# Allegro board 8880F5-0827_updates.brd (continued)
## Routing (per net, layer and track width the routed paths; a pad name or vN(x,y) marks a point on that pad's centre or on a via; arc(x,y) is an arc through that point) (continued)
S4_DPS_F_002: length 10.1
  TOP w0.231: 320.65,169.55 321.72,169.55 323.03,170.86 SITE4.3
  TOP w0.508: 320.65,169.55 317.98,166.88 v1(317.98,165.75)
  vias: v1(316.32,162.9) v1(317.98,163.71) v1(511.6,278.76) v1(511.6,276.86)
S4_DPS_F_003: length 63.1
  TOP w0.231: SITE4.107 332.23,200.11 331.69,200.65 331.69,201.16 ; 339.73,169.66 338.57,169.66 336.63,171.59 SITE4.37 ; 329.28,168.85 328.63,169.5 SITE4.17 ; SITE4.145 313.08,188.43 312.83,188.18 ; 314.63,181.63 SITE4.162 ; 347.84,185.53 346.94,186.43 SITE4.71 ; 345.2,182.93 344.9,183.23 SITE4.63
  TOP w0.381: v1(331.94,204.54) 331.69,204.28 331.69,201.16
  TOP w0.508: 312.83,188.18 312.58,187.93 v1(311.44,187.93) ; v1(351.22,181.37) 348.11,181.37 346.8,182.68 345.45,182.68 345.2,182.93 ; v1(351.22,183.91) 349.45,183.91 347.84,185.53 ; 314.63,181.63 314.37,181.63 312.59,183.41 v1(311.44,183.41) ; v1(342.36,165.75) 342.36,167.02 339.73,169.66 ; v1(329.28,165.75) 329.28,168.85
  vias: v1(309.4,187.93) v1(309.4,183.41) v1(329.28,163.71) v1(331.54,192.61) v1(331.94,206.58) v1(342.36,163.71) v1(353.27,183.91) v1(353.27,181.37) v1(464.57,192.28) v1(501.86,278.76) v1(501.86,276.86)
S4_DPS_F_006: length 9.6
  TOP w0.231: SITE4.72 347.92,186.83 348.55,186.19
  TOP w0.508: 348.55,186.19 349.56,185.18 v1(351.22,185.18)
  vias: v1(339,186.67) v1(353.27,185.18) v1(478.58,262.25) v1(478.58,260.35)
S4_DPS_F_007: length 19
  TOP w0.231: SITE4.78 344.15,189.23 344.37,189.01 ; SITE4.97 336.23,200.71 339.65,204.13 v1(339.65,204.54)
  TOP w0.508: v1(351.22,189.5) 350.8,189.5 350.31,189.01 344.37,189.01
  vias: v1(339.65,206.58) v1(353.27,189.5) v1(528.11,262.25) v1(528.11,260.35)
S4_DPS_F_009: length 8.8
  TOP w0.231: 332.26,201.12 332.26,200.9 332.63,200.53 SITE4.106
  TOP w0.381: 332.26,201.12 332.26,203.82 332.83,204.39 v1(332.83,204.54)
  vias: v1(332.83,206.58) v1(333.61,207.66) v1(495.09,262.25) v1(495.09,260.35)
S4_DPS_F_010: length 8.6
  TOP w0.231: SITE4.111 330.63,200.15 331.05,200.57 331.05,201.13
  TOP w0.381: 331.05,201.13 v1(331.05,204.54)
  vias: v1(330.34,193.59) v1(331.05,206.58) v1(485.35,262.25) v1(485.35,260.35)
S4_DPS_F_011: length 17.6
  TOP w0.231: SITE4.119 327.43,197.79 327.64,198.01 ; SITE4.139 314.87,190.83 312.01,193.69 v1(311.44,193.69)
  TOP w0.508: v1(327.57,204.54) 327.64,204.47 327.64,198.01
  vias: v1(309.4,193.69) v1(327.57,206.58) v1(518.37,262.25) v1(518.37,260.35)
S4_DPS_F_012: length 8
  TOP w0.231: 312.2,188.83 SITE4.144
  TOP w0.508: 312.2,188.83 311.81,188.83 v1(311.44,189.2)
  vias: v1(309.4,189.2) v1(468.84,262.25) v1(468.84,260.35)
S4_DPS_F_013:
  vias: v1(117.33,249.71) v1(117.33,247.8) v1(452.62,188.98) v1(457.25,190.45) v1(474.87,173.79) v1(474.89,161.55) v1(474.99,175.15) v1(478.43,173.74) v1(478.43,161.55) v1(478.53,175.15) v1(480.97,161.55) v1(481.07,175.15) v1(482.1,197.87) v1(483.51,161.55) v1(483.61,175.15) v1(489.86,169.47) v1(490.1,183.24)
S4_ISP00+: length 163.7
  TOP w0.086: v1(353.81,185.88) 353.35,186.33 350.29,186.33 349.31,187.31 344.06,187.31 343.98,187.23 SITE4.73
  L30_SIGNAL w0.071: v1(307.81,134.11) 307.81,135.47 307.88,135.54 312.56,135.54 313.46,136.44 313.46,137.88 312.55,138.79 297.11,138.79 293.94,141.95 293.94,193.09 297.8,196.95 305.85,196.95 307.89,198.98 325.62,198.98 327.67,196.93 339.21,196.93 349.79,186.35 353.73,186.35 353.81,186.28 v1(353.81,185.88)
  BOTTOM w0.119: v1(307.81,134.11) UNK4K43.7
S4_ISP00-: length 163.7
  TOP w0.086: v1(353.81,187.02) 353.35,186.57 350.39,186.57 349.41,187.55 344.06,187.55 343.98,187.63 SITE4.74
  L30_SIGNAL w0.071: v1(307.81,137.16) 307.81,135.81 307.88,135.74 312.48,135.74 313.26,136.52 313.26,137.8 312.47,138.59 297.03,138.59 293.74,141.87 293.74,193.17 297.72,197.14 305.76,197.14 307.8,199.18 325.7,199.18 327.75,197.13 339.29,197.13 349.87,186.55 353.73,186.55 353.81,186.62 v1(353.81,187.02)
  BOTTOM w0.119: v1(307.81,137.16) UNK4K43.2
S4_ISP14+: length 147
  TOP w0.086: SITE4.112 330.23,197.78 330.15,197.86 330.15,206.59 331.48,207.92 331.48,209.45 v1(331.93,209.9)
  L28_SIGNAL w0.071: v1(312.21,131.64) 312.21,135.43 312.07,135.56 298.39,135.56 293.47,140.48 293.47,196.62 303.51,206.65 303.51,212.34 304.92,213.75 329.77,213.75 331.46,212.06 331.46,209.97 331.53,209.9 v1(331.93,209.9)
S4_ISP14-: length 146
  TOP w0.086: v1(330.79,209.9) 331.24,209.45 331.24,208.02 329.91,206.69 329.91,197.86 329.83,197.78 SITE4.113
  L28_SIGNAL w0.071: v1(330.79,209.9) 331.19,209.9 331.26,209.97 331.26,211.98 329.69,213.55 305,213.55 303.71,212.26 303.71,206.57 293.67,196.53 293.67,140.56 298.47,135.76 312.08,135.76 312.21,135.89 v1(312.21,139.64)
S4_ISP_1LOCK:
  vias: v1(309.91,185.39)
S4_M_DPS_F_001: length 45.2
  TOP w0.231: 330.63,170.54 SITE4.22 ; 313.24,187.18 313.7,187.63 SITE4.147 ; SITE4.39 337.43,171.49 338.54,170.37 340.57,170.37 ; SITE4.104 333.43,203.21 ; 346.49,183.63 SITE4.64
  TOP w0.381: v1(334.61,204.54) 334.61,204.39 333.43,203.21
  TOP w0.508: v1(330.17,165.75) 330.17,168.96 330.38,169.17 330.38,170.28 330.63,170.54 ; 313.24,187.18 312.72,186.66 v1(311.44,186.66) ; 346.49,183.63 347.49,183.63 348.48,182.64 v1(351.22,182.64) ; 340.57,170.37 343.63,167.31 v1(343.63,165.75)
  vias: v1(309.4,186.66) v1(330.17,163.71) v1(334.61,206.58) v1(343.63,163.71) v1(353.27,182.64) v1(518.37,295.27) v1(518.37,293.37)
S4_PS9G_DCH001: length 3.7
  TOP w0.231: SITE4.18 329.03,170.23 v1(329.63,169.63)
S4_PS9G_DCH002: length 2.2
  TOP w0.231: v1(329.63,171.03) 329.43,171.23 SITE4.19
S4_PS9G_DCH003: length 2.2
  TOP w0.231: v1(331.23,171.03) 331.43,171.23 SITE4.24
S4_PS9G_DCH004: length 2.2
  TOP w0.231: v1(337.63,175.23) 337.83,175.03 SITE4.40
S4_PS9G_DCH005: length 2.2
  TOP w0.231: v1(344.43,175.83) 344.23,176.03 SITE4.45
S4_PS9G_DCH006: length 3.7
  TOP w0.231: v1(345.83,175.83) 345.23,176.43 SITE4.46
S4_PS9G_DCH007: length 5.3
  TOP w0.231: SITE4.47 346.22,176.83 v1(347.22,175.83)
S4_PS9G_DCH009: length 2.2
  TOP w0.231: SITE4.49 344.23,177.63 v1(344.43,177.43)
S4_PS9G_DCH010: length 3.7
  TOP w0.231: v1(345.83,177.43) 345.23,178.03 SITE4.50
S4_PS9G_DCH011: length 5.3
  TOP w0.231: v1(347.22,177.43) 346.22,178.43 SITE4.51
S4_PS9G_DCH014: length 3.7
  TOP w0.231: SITE4.54 345.23,179.63 v1(345.83,179.03)
S4_PS9G_DCH015: length 5.3
  TOP w0.231: SITE4.55 346.22,180.03 v1(347.22,179.03)
S4_PS9G_DCH022: length 5.3
  TOP w0.231: v1(347.22,185.03) 347.05,185.03 346.05,184.03 SITE4.65
S4_PS9G_DCH023: length 2.5
  TOP w0.231: SITE4.66 344.03,184.43 344.43,184.83 v1(344.43,185.03)
S4_PS9G_DCH027: length 3.9
  TOP w0.231: SITE4.70 344.83,186.03 v1(345.83,185.03)
S4_PS9G_DCH028: length 2.3
  TOP w0.231: SITE4.77 340.6,188.83 v1(340.23,188.46)
S4_PS9G_DCH029: length 2.2
  TOP w0.119: SITE4.118 v1(327.83,193.92)
S4_PS9G_DCH030: length 9.2
  TOP w0.231: SITE4.148 317.62,187.23 317.3,186.91 314.16,186.91 312.63,185.39 v1(310.91,185.39)
S4_PS9G_DCH035: length 5.3
  TOP w0.231: v1(314.43,186.23) 315.44,185.23 SITE4.153
S4_PS9G_DCH036: length 2.2
  TOP w0.231: v1(321.43,185.03) 321.23,184.83 SITE4.154
S4_PS9G_DCH037: length 2.2
  TOP w0.231: v1(317.23,184.63) 317.43,184.43 SITE4.155
S4_PS9G_DCH038: length 3.7
  TOP w0.231: SITE4.156 316.43,184.03 v1(315.83,184.63)
S4_PS9G_DCH039: length 5.3
  TOP w0.231: v1(314.43,184.63) 315.44,183.63 SITE4.157
S4_PS9G_DCH040: length 2.2
  TOP w0.231: SITE4.158 321.23,183.23 v1(321.43,183.43)
S4_RLY_001:
  vias: v1(375.22,163.39) v1(415.1,163.64)
S4_RLY_003:
  vias: v1(388.43,163.64) v1(401.89,163.64)
S4_RLY_005:
  vias: v1(375.22,180.15) v1(388.43,180.15)
S4_RLY_007:
  vias: v1(415.61,188.92)
S4_RLY_008:
  vias: v1(375.73,202.38) v1(401.89,180.15)
S4_RLY_016:
  vias: v1(376.23,209.11) v1(392.24,202.38)
S4_RLY_018:
  vias: v1(312.25,216.97)
S4_RLY_021:
  vias: v1(388.43,146.88) v1(402.14,146.88)
S4_RLY_022:
  vias: v1(384.36,131.89) v1(397.57,131.89)
S4_RLY_023:
  vias: v1(410.78,131.89)
S4_RLY_025:
  vias: v1(304.82,146.05) v1(318.32,131.64)
S4_RLY_026:
  vias: v1(346.27,138.37)
S4_RLY_030:
  vias: v1(415.6,146.88)
S4_RLY_043:
  vias: v1(304.61,131.64)
S4_SCAN_DCH008: length 2.2
  TOP w0.231: v1(340.23,177.03) 340.43,177.23 SITE4.48
S4_SCAN_DCH012: length 2.2
  TOP w0.231: SITE4.52 340.43,178.83 v1(340.23,178.63)
S4_SCAN_DCH013: length 2.2
  TOP w0.231: SITE4.53 344.23,179.23 v1(344.43,179.03)
S4_SCAN_DCH016: length 2.2
  TOP w0.231: v1(340.23,180.23) 340.43,180.43 SITE4.56
S4_SCAN_DCH017: length 2.2
  TOP w0.231: v1(344.43,180.63) 344.23,180.83 SITE4.57
S4_SCAN_DCH018: length 3.7
  TOP w0.231: v1(345.83,180.63) 345.23,181.23 SITE4.58
S4_SCAN_DCH019: length 5.3
  TOP w0.231: SITE4.59 346.22,181.63 v1(347.22,180.63)
S4_SCAN_DCH020: length 2.2
  TOP w0.231: v1(340.23,181.83) 340.43,182.03 SITE4.60
S4_SCAN_DCH021: length 2.2
  TOP w0.231: v1(344.43,182.23) 344.23,182.43 SITE4.61
S4_SCAN_DCH024: length 2.2
  TOP w0.231: v1(340.23,184.63) 340.43,184.83 SITE4.67
S4_SCAN_DCH025: length 3.7
  TOP w0.231: SITE4.68 339.43,185.23 v1(338.83,184.63)
S4_SCAN_DCH026: length 5.3
  TOP w0.231: SITE4.69 338.44,185.63 v1(337.44,184.63)
S4_SCAN_DCH031: length 3.7
  TOP w0.231: v1(322.83,187.43) 322.23,186.83 SITE4.149
S4_SCAN_DCH032: length 5.3
  TOP w0.231: SITE4.150 323.22,186.43 v1(324.22,187.43)
S4_SCAN_DCH033: length 2.2
  TOP w0.231: SITE4.151 317.43,186.03 v1(317.23,186.23)
S4_SCAN_DCH034: length 3.7
  TOP w0.231: v1(315.83,186.23) 316.43,185.63 SITE4.152
S4_SPI_1_SCK:
  vias: v1(480.07,175.15)
S4_SPI_1_SDO:
  vias: v1(455.94,166.12)
S4_SPI_2_CSN:
  vias: v1(475.87,173.79)
S4_SPI_2_SCK:
  vias: v1(479.97,161.55)
S4_SPI_2_SDO:
  vias: v1(451.87,166.12)
S4_SPI_11_SDO:
  vias: v1(456.94,166.12) v1(482.61,175.15)
S4_SPI_22_SDI:
  vias: v1(477.43,173.74)
S4_SPI_22_SDO:
  vias: v1(452.87,166.12) v1(482.51,161.55)
S4_SPI_CSN: length 2.2
  TOP w0.231: v1(339.23,171.03) 339.03,171.23 SITE4.43
S4_SPI_SCK: length 2.2
  TOP w0.231: SITE4.42 338.63,175.03 v1(338.83,175.23)
S4_SPI_SDI: length 3.7
  TOP w0.231: SITE4.44 339.43,176.03 v1(338.83,176.63)
S4_SPI_SDO: length 3.7
  TOP w0.231: v1(337.63,176.63) 338.23,176.03 SITE4.41
S4_XTAL_IN: length 2.5
  TOP w0.119: SITE4.109 331.43,198.31 v1(331.63,198.51)
  vias: v1(306.85,211.67)
S4_XTAL_OUT: length 3.7
  TOP w0.231: SITE4.110 331.03,199.03 v1(331.63,199.63)
  vias: v1(306.85,216.97)
UDBGND:
  vias: v1(13.3,262.13) v1(13.55,259.69) v1(23.86,130.71) v1(24.11,128.27) v1(36.83,129.86) v1(117.69,130.81) v1(118.49,128.27) v1(128.57,149.86) v1(128.57,146.05) v1(128.57,138.43) v1(128.57,134.62) v1(130.51,142.24) v1(224.37,298.45) v1(225.17,295.91) v1(452.68,137.92) v1(452.68,134.11) v1(452.68,130.3) v1(454.61,145.54) v1(454.61,141.73) v1(473.29,130.81) v1(474.09,128.27) v1(484.87,130.71) v1(485.12,128.27) v1(512.11,238.76) v1(512.11,234.95) v1(512.11,231.14) v1(512.11,227.33) v1(548.37,300.89) v1(548.62,298.45) v1(557.36,300.99) v1(558.16,298.45)
UT1_UP5V:
  vias: v1(11.05,259.69) v1(11.6,262.13) v1(21.61,128.27) v1(22.16,130.71) v1(36.83,135.89) v1(36.83,133.85) v1(115.19,128.27) v1(115.99,130.81) v1(175.7,264.1) v1(175.7,250.38) v1(175.7,236.67) v1(175.7,222.95) v1(175.7,209.49) v1(175.7,195.52) v1(175.7,182.06) v1(175.7,168.6) v1(175.7,154.88) v1(175.7,141.67) v1(192.47,264.1) v1(192.47,250.38) v1(192.47,236.67) v1(192.47,222.95) v1(192.47,209.49) v1(192.47,195.52) v1(192.47,182.06) v1(192.47,168.6) v1(192.47,154.88) v1(208.98,264.1) v1(209.23,250.38) v1(209.23,236.67) v1(209.23,222.95) v1(209.23,209.49) v1(209.23,195.52) v1(209.49,182.06) v1(209.49,168.6) v1(209.49,155.13) v1(209.49,155.13) v1(221.87,295.91) v1(222.67,298.45) v1(232.25,271.67) v1(232.25,211.67) v1(244.8,288.61) v1(250.5,296.86) v1(256.73,132.14) v1(263.71,296.86) v1(269.69,135.19) v1(273.24,272.1) v1(277.17,296.86) v1(282.9,147.38) v1(290.64,296.86) v1(293.31,272.1) v1(303.84,296.86) v1(304.61,139.64) v1(304.82,154.05) v1(312.25,271.67) v1(312.25,211.67) v1(317.05,296.86) v1(318.32,139.64) v1(330.51,296.86) v1(343.98,296.86) v1(354.27,138.37) v1(369.38,265.11) v1(369.38,249.11) v1(369.38,232.6) v1(369.63,297.12) v1(369.63,281.11) v1(375.22,188.15) v1(375.22,171.39) v1(376.23,217.11) v1(383.09,297.12) v1(383.09,281.11) v1(383.09,265.11) v1(383.09,249.11) v1(383.09,232.85) v1(383.73,202.38) v1(384.36,139.89) v1(388.43,188.15) v1(388.43,171.64) v1(388.43,154.88) v1(389.7,217.36) v1(396.55,297.12) v1(396.55,281.11) v1(396.55,265.37) v1(396.55,249.11) v1(396.55,233.11) v1(397.57,139.89) v1(400.24,202.38) v1(401.89,188.15) v1(401.89,171.64) v1(402.14,154.88) v1(403.41,217.61) v1(410.27,265.37) v1(410.52,297.12) v1(410.52,281.37) v1(410.52,249.11) v1(410.78,139.89) v1(415.1,171.64) v1(415.6,154.88) v1(423.61,188.92) v1(470.79,128.27) v1(471.59,130.81) v1(482.62,128.27) v1(483.17,130.71) v1(546.12,298.45) v1(546.67,300.89) v1(554.86,298.45) v1(555.66,300.99)
N16868442:
  vias: v1(36.83,132.85) v1(36.83,131.76)
N24574244:
  vias: v1(88.53,207.41)
N24574268:
  vias: v1(88.77,221.18)
N24574272:
  vias: v1(93.83,221.18)
N24574311:
  vias: v1(102.1,215.5)
N24574376:
  vias: v1(102.2,229.1)
N24574578:
  vias: v1(93.83,207.46)
N24787993:
  vias: v1(185.21,289.56)
N24789529:
  vias: v1(118.32,288.29)
N24789779:
  vias: v1(168.7,289.56)
N25330426:
  vias: v1(168.7,273.05)
N25334489:
  vias: v1(185.21,273.05)
N25337760:
  vias: v1(201.21,273.05)
N25339188:
  vias: v1(201.21,289.56)
N25462044:
  vias: v1(175.47,273.05)
N25462912:
  vias: v1(158.96,273.05)
N25463486:
  vias: v1(191.48,289.56)
N25464528:
  vias: v1(158.96,289.56)
N25465136:
  vias: v1(175.47,289.56)
N26125600: length 3
  BOTTOM w0.119: K25.3 211.07,244.98 211.54,245.46 R55.2
N26125602: length 3
  BOTTOM w0.119: K25.4 211.07,242.78 211.54,242.31 R56.1
N26125604: length 3
  BOTTOM w0.119: K25.6 199.4,244.98 198.92,245.46 R57.2
N26125606: length 3
  BOTTOM w0.119: K25.5 199.4,242.78 198.92,242.31 R58.1
N26125622: length 3
  BOTTOM w0.119: K26.3 177.54,231.27 178.01,231.74 R59.2
N26125624: length 3
  BOTTOM w0.119: R60.1 178.01,228.6 177.54,229.07 K26.4
N26125626: length 3
  BOTTOM w0.119: R61.2 165.4,231.74 165.87,231.27 K26.6
N26125628: length 3
  BOTTOM w0.119: R62.1 165.4,228.6 165.87,229.07 K26.5
N26125644: length 3
  BOTTOM w0.119: K27.5 182.63,242.78 182.16,242.31 R66.1
N26125646: length 3
  BOTTOM w0.119: K27.6 182.63,244.98 182.16,245.46 R65.2
N26125685: length 3
  BOTTOM w0.119: K22.6 199.4,231.27 198.92,231.74 R45.2
N26125687: length 3
  BOTTOM w0.119: R46.1 198.92,228.6 199.4,229.07 K22.5
N26125689: length 3
  BOTTOM w0.119: K23.3 177.54,217.55 178.01,218.02 R47.2
N26125691: length 3
  BOTTOM w0.119: K23.4 177.54,215.35 178.01,214.88 R48.1
N26125693: length 3
  BOTTOM w0.119: K23.6 165.87,217.55 165.4,218.02 R49.2
N26125695: length 3
  BOTTOM w0.119: R50.1 165.4,214.88 165.87,215.35 K23.5
N26125711: length 3
  BOTTOM w0.119: R51.2 194.78,231.74 194.3,231.27 K24.3
N26125713: length 3
  BOTTOM w0.119: R52.1 194.78,228.6 194.3,229.07 K24.4
N26125715: length 3
  BOTTOM w0.119: K24.6 182.63,231.27 182.16,231.74 R53.2
N26125717: length 3
  BOTTOM w0.119: R54.1 182.16,228.6 182.63,229.07 K24.5
N26125746: length 3
  BOTTOM w0.119: K22.3 211.07,231.27 211.54,231.74 R102.2
N26125748: length 3
  BOTTOM w0.119: R103.1 211.54,228.6 211.07,229.07 K22.4
N26125750: length 3
  BOTTOM w0.119: K27.3 194.3,244.98 194.78,245.46 R104.2
N26125752: length 3
  BOTTOM w0.119: R105.1 194.78,242.31 194.3,242.78 K27.4
N26138300:
  vias: v1(113.29,230.12)
N26138322:
  vias: v1(110.24,230.12)
N26323523: length 3
  BOTTOM w0.119: R71.2 194.78,259.17 194.3,258.7 K17.3
N26323525: length 3
  BOTTOM w0.119: R72.1 194.78,256.03 194.3,256.5 K17.4
N26323527: length 3
  BOTTOM w0.119: R74.1 182.16,256.03 182.63,256.5 K17.5
N26323529: length 3
  BOTTOM w0.119: K17.6 182.63,258.7 182.16,259.17 R73.2
N26323531: length 3
  BOTTOM w0.119: R75.2 211.29,259.17 210.81,258.7 K21.3
N26323533: length 3
  BOTTOM w0.119: K21.4 210.81,256.5 211.29,256.03 R76.1
N26323535: length 3
  BOTTOM w0.119: K21.5 199.14,256.5 198.67,256.03 R78.1
N26323537: length 3
  BOTTOM w0.119: K21.6 199.14,258.7 198.67,259.17 R77.2
N26323539: length 3
  BOTTOM w0.119: R79.2 178.01,259.17 177.54,258.7 K29.3
N26323541: length 3
  BOTTOM w0.119: K29.4 177.54,256.5 178.01,256.03 R80.1
N26323543: length 3
  BOTTOM w0.119: K29.6 165.87,258.7 165.4,259.17 R43.2
N26323545: length 3
  BOTTOM w0.119: R44.1 165.4,256.03 165.87,256.5 K29.5
N26323547: length 3
  BOTTOM w0.119: K30.3 177.54,244.98 178.01,245.46 R63.2
N26323549: length 3
  BOTTOM w0.119: K30.4 177.54,242.78 178.01,242.31 R64.1
N26323551: length 3
  BOTTOM w0.119: K30.5 165.87,242.78 165.4,242.31 R101.1
N26323553: length 3
  BOTTOM w0.119: R100.2 165.4,245.46 165.87,244.98 K30.6
N26325241: length 3
  BOTTOM w0.119: K16.3 239.4,286.77 239.87,286.3 R67.2
N26325243: length 3
  BOTTOM w0.119: R68.1 236.72,286.3 237.2,286.77 K16.4
N26325245: length 3
  BOTTOM w0.119: R70.1 236.72,298.92 237.2,298.44 K16.5
N26325247: length 3
  BOTTOM w0.119: K16.6 239.4,298.44 239.87,298.92 R69.2
N26326910: length 3
  BOTTOM w0.119: R30.1 298.71,286.55 298.24,287.03 K6.5
N26326941: length 3
  BOTTOM w0.119: R27.2 295.56,299.17 296.04,298.7 K6.3
N26326943: length 3
  BOTTOM w0.119: R28.1 298.71,299.17 298.24,298.7 K6.4
N26326945: length 3
  BOTTOM w0.119: R29.2 295.56,286.55 296.04,287.03 K6.6
N26326947: length 3
  BOTTOM w0.119: R34.1 285.25,286.55 284.77,287.03 K7.5
N26326959: length 3
  BOTTOM w0.119: R31.2 282.1,299.17 282.57,298.7 K7.3
N26326961: length 3
  BOTTOM w0.119: K7.4 284.77,298.7 285.25,299.17 R32.1
N26326963: length 3
  BOTTOM w0.119: R33.2 282.1,286.55 282.57,287.03 K7.6
N26327095: length 3
  BOTTOM w0.119: K11.3 255.9,298.7 255.43,299.17 R39.2
N26327097: length 3
  BOTTOM w0.119: K11.4 258.1,298.7 258.58,299.17 R40.1
N26327099: length 3
  BOTTOM w0.119: K8.5 271.31,287.03 271.78,286.55 R38.1
N26327103: length 3
  BOTTOM w0.119: R37.2 268.64,286.55 269.11,287.03 K8.6
N26327105: length 3
  BOTTOM w0.119: R41.2 255.43,286.55 255.9,287.03 K11.6
N26327107: length 3
  BOTTOM w0.119: K11.5 258.1,287.03 258.58,286.55 R42.1
N26328546: length 3
  BOTTOM w0.119: K5.5 311.44,287.03 311.92,286.55 R26.1
N26328550: length 3
  BOTTOM w0.119: R23.2 308.77,299.17 309.24,298.7 K5.3
N26328552: length 3
  BOTTOM w0.119: K5.4 311.44,298.7 311.92,299.17 R24.1
N26328554: length 3
  BOTTOM w0.119: K5.6 309.24,287.03 308.77,286.55 R25.2
N26330264: length 3
  BOTTOM w0.119: K3.5 324.65,287.03 325.12,286.55 R18.1
N26330266: length 3
  BOTTOM w0.119: K3.6 322.45,287.03 321.98,286.55 R17.2
N26330268: length 3
  BOTTOM w0.119: R16.1 325.12,299.17 324.65,298.7 K3.4
N26330270: length 3
  BOTTOM w0.119: R15.2 321.98,299.17 322.45,298.7 K3.3
N26330276: length 3
  BOTTOM w0.119: R10.1 352.05,286.55 351.58,287.03 K1.5
N26330278: length 3
  BOTTOM w0.119: K1.6 349.38,287.03 348.9,286.55 R9.2
N26330280: length 3
  BOTTOM w0.119: K1.4 351.58,298.7 352.05,299.17 R8.1
N26330282: length 3
  BOTTOM w0.119: R7.2 348.9,299.17 349.38,298.7 K1.3
N26330286: length 3
  BOTTOM w0.119: K2.3 335.91,298.7 335.44,299.17 R11.2
N26330288: length 3
  BOTTOM w0.119: K2.4 338.11,298.7 338.59,299.17 R12.1
N26330290: length 3
  BOTTOM w0.119: R22.1 285.24,282.41 285.71,281.93 K4.5
N26330294: length 3
  BOTTOM w0.119: R19.2 288.38,269.79 287.91,270.26 K4.3
N26330296: length 3
  BOTTOM w0.119: K4.4 285.71,270.26 285.24,269.79 R20.1
N26330298: length 3
  BOTTOM w0.119: R21.2 288.38,282.41 287.91,281.93 K4.6
N26330300: length 3
  BOTTOM w0.119: R14.1 338.59,286.55 338.11,287.03 K2.5
N26330302: length 3
  BOTTOM w0.119: K2.6 335.91,287.03 335.44,286.55 R13.2
N26336814:
  vias: v1(123.12,241.1)
N26336816:
  vias: v1(127.7,241.1)
N26336828:
  vias: v1(222.38,273.82) v1(222.38,272.66) v1(224.65,271.67)
N26336832:
  vias: v1(222.38,275.98) v1(222.38,274.82) v1(224.65,276.97)
N26336834:
  vias: v1(221.21,276.98) v1(222.38,276.98)
N26336836:
  vias: v1(221.21,271.66) v1(222.38,271.66)
N26336892:
  vias: v1(127.75,225.81)
N26336894:
  vias: v1(127.75,233.43)
N26337539:
  vias: v1(96.27,241.05)
N26337547:
  vias: v1(96.27,233.43)
N26486525: length 3
  BOTTOM w0.119: UNK2K25.3 415.92,250.95 415.45,251.42 UNK2R55.2
N26486526: length 3
  BOTTOM w0.119: UNK2K25.4 418.12,250.95 418.6,251.42 UNK2R56.1
N26486527: length 3
  BOTTOM w0.119: UNK2K25.6 415.92,239.27 415.45,238.8 UNK2R57.2
N26486528: length 3
  BOTTOM w0.119: UNK2R58.1 418.6,238.8 418.12,239.27 UNK2K25.5
N26486530: length 3
  BOTTOM w0.119: UNK2R59.2 374.3,234.91 374.78,234.44 UNK2K26.3
N26486531: length 3
  BOTTOM w0.119: UNK2K26.4 376.98,234.44 377.45,234.91 UNK2R60.1
N26486532: length 3
  BOTTOM w0.119: UNK2K26.6 374.78,222.76 374.3,222.29 UNK2R61.2
N26486533: length 3
  BOTTOM w0.119: UNK2R62.1 377.45,222.29 376.98,222.76 UNK2K26.5
N26486535: length 3
  BOTTOM w0.119: UNK2K27.5 390.69,223.02 391.16,222.55 UNK2R66.1
N26486536: length 3
  BOTTOM w0.119: UNK2R65.2 388.02,222.55 388.49,223.02 UNK2K27.6
N26486543: length 3
  BOTTOM w0.119: UNK2R45.2 401.48,222.8 401.95,223.27 UNK2K22.6
N26486544: length 3
  BOTTOM w0.119: UNK2R46.1 404.63,222.8 404.15,223.27 UNK2K22.5
N26486545: length 3
  BOTTOM w0.119: UNK2K23.3 408.81,219.45 408.34,219.92 UNK2R47.2
N26486546: length 3
  BOTTOM w0.119: UNK2R48.1 411.48,219.92 411.01,219.45 UNK2K23.4
N26486547: length 3
  BOTTOM w0.119: UNK2R49.2 408.34,207.31 408.81,207.78 UNK2K23.6
N26486548: length 3
  BOTTOM w0.119: UNK2R50.1 411.48,207.31 411.01,207.78 UNK2K23.5
N26486550: length 3
  BOTTOM w0.119: UNK2R51.2 394.62,219.67 395.1,219.2 UNK2K24.3
N26486551: length 3
  BOTTOM w0.119: UNK2K24.4 397.3,219.2 397.77,219.67 UNK2R52.1
N26486552: length 3
  BOTTOM w0.119: UNK2K24.6 395.1,207.52 394.62,207.05 UNK2R53.2
N26486553: length 3
  BOTTOM w0.119: UNK2K24.5 397.3,207.52 397.77,207.05 UNK2R54.1
N26486568: length 3
  BOTTOM w0.119: UNK2K22.3 401.95,234.94 401.48,235.42 UNK2R102.2
N26486569: length 3
  BOTTOM w0.119: UNK2K22.4 404.15,234.94 404.63,235.42 UNK2R103.1
N26486570: length 3
  BOTTOM w0.119: UNK2R104.2 388.02,235.16 388.49,234.69 UNK2K27.3
N26486571: length 3
  BOTTOM w0.119: UNK2K27.4 390.69,234.69 391.16,235.16 UNK2R105.1
N26486686:
  vias: v1(465.57,235.71)
N26486691:
  vias: v1(468.62,235.71)
N26486726: length 3
  BOTTOM w0.119: UNK2R71.2 401.48,299.42 401.95,298.95 UNK2K17.3
N26486727: length 3
  BOTTOM w0.119: UNK2K17.4 404.15,298.95 404.63,299.42 UNK2R72.1
N26486728: length 3
  BOTTOM w0.119: UNK2R74.1 404.63,286.81 404.15,287.28 UNK2K17.5
N26486729: length 3
  BOTTOM w0.119: UNK2K17.6 401.95,287.28 401.48,286.81 UNK2R73.2
N26486730: length 3
  BOTTOM w0.119: UNK2K21.3 375.03,298.95 374.56,299.42 UNK2R75.2
N26486731: length 3
  BOTTOM w0.119: UNK2R76.1 377.7,299.42 377.23,298.95 UNK2K21.4
N26486732: length 3
  BOTTOM w0.119: UNK2K21.5 377.23,287.28 377.7,286.81 UNK2R78.1
N26486733: length 3
  BOTTOM w0.119: UNK2R77.2 374.56,286.81 375.03,287.28 UNK2K21.6
N26486734: length 3
  BOTTOM w0.119: UNK2K29.3 388.49,250.95 388.02,251.42 UNK2R79.2
N26486735: length 3
  BOTTOM w0.119: UNK2R80.1 391.16,251.42 390.69,250.95 UNK2K29.4
N26486736: length 3
  BOTTOM w0.119: UNK2R43.2 388.02,238.8 388.49,239.27 UNK2K29.6
N26486737: length 3
  BOTTOM w0.119: UNK2R44.1 391.16,238.8 390.69,239.27 UNK2K29.5
N26486738: length 3
  BOTTOM w0.119: UNK2R63.2 401.48,251.42 401.95,250.95 UNK2K30.3
N26486739: length 3
  BOTTOM w0.119: UNK2R64.1 404.63,251.42 404.15,250.95 UNK2K30.4
N26486740: length 3
  BOTTOM w0.119: UNK2K30.5 404.15,239.27 404.63,238.8 UNK2R101.1
N26486741: length 3
  BOTTOM w0.119: UNK2K30.6 401.95,239.27 401.48,238.8 UNK2R100.2
N26486822: length 3
  BOTTOM w0.119: UNK2K16.3 375.03,282.95 374.56,283.42 UNK2R67.2
N26486823: length 3
  BOTTOM w0.119: UNK2K16.4 377.23,282.95 377.7,283.42 UNK2R68.1
N26486824: length 3
  BOTTOM w0.119: UNK2R70.1 377.7,270.81 377.23,271.28 UNK2K16.5
N26486825: length 3
  BOTTOM w0.119: UNK2K16.6 375.03,271.28 374.56,270.81 UNK2R69.2
N26486847: length 3
  BOTTOM w0.119: UNK2R30.1 418.6,271.06 418.12,271.53 UNK2K6.5
N26486849: length 3
  BOTTOM w0.119: UNK2K6.3 415.92,283.2 415.45,283.68 UNK2R27.2
N26486850: length 3
  BOTTOM w0.119: UNK2K6.4 418.12,283.2 418.6,283.68 UNK2R28.1
N26486851: length 3
  BOTTOM w0.119: UNK2R29.2 415.45,271.06 415.92,271.53 UNK2K6.6
N26486852: length 3
  BOTTOM w0.119: UNK2K7.5 404.15,271.28 404.63,270.81 UNK2R34.1
N26486854: length 3
  BOTTOM w0.119: UNK2R31.2 401.48,283.42 401.95,282.95 UNK2K7.3
N26486855: length 3
  BOTTOM w0.119: UNK2R32.1 404.63,283.42 404.15,282.95 UNK2K7.4
N26486856: length 3
  BOTTOM w0.119: UNK2R33.2 401.48,270.81 401.95,271.28 UNK2K7.6
N26486898: length 3
  BOTTOM w0.119: UNK2R39.2 388.02,283.42 388.49,282.95 UNK2K11.3
N26486899: length 3
  BOTTOM w0.119: UNK2K11.4 390.69,282.95 391.16,283.42 UNK2R40.1
N26486900: length 3
  BOTTOM w0.119: UNK2K8.5 390.69,287.28 391.16,286.81 UNK2R38.1
N26486902: length 3
  BOTTOM w0.119: UNK2K8.6 388.49,287.28 388.02,286.81 UNK2R37.2
N26486903: length 3
  BOTTOM w0.119: UNK2K11.6 388.49,271.28 388.02,270.81 UNK2R41.2
N26486904: length 3
  BOTTOM w0.119: UNK2R42.1 391.16,270.81 390.69,271.28 UNK2K11.5
N26486946: length 3
  BOTTOM w0.119: UNK2K5.5 417.87,255.53 418.34,255.06 UNK2R26.1
N26486948: length 3
  BOTTOM w0.119: UNK2R23.2 415.2,267.67 415.67,267.2 UNK2K5.3
N26486949: length 3
  BOTTOM w0.119: UNK2K5.4 417.87,267.2 418.34,267.67 UNK2R24.1
N26486950: length 3
  BOTTOM w0.119: UNK2K5.6 415.67,255.53 415.2,255.06 UNK2R25.2
N26486971: length 3
  BOTTOM w0.119: UNK2K3.5 404.15,255.53 404.63,255.06 UNK2R18.1
N26486972: length 3
  BOTTOM w0.119: UNK2K3.6 401.95,255.53 401.48,255.06 UNK2R17.2
N26486973: length 3
  BOTTOM w0.119: UNK2K3.4 404.15,267.2 404.63,267.67 UNK2R16.1
N26486974: length 3
  BOTTOM w0.119: UNK2R15.2 401.48,267.67 401.95,267.2 UNK2K3.3
N26486977: length 3
  BOTTOM w0.119: UNK2R10.1 418.6,286.81 418.12,287.28 UNK2K1.5
N26486978: length 3
  BOTTOM w0.119: UNK2R9.2 415.45,286.81 415.92,287.28 UNK2K1.6
N26486979: length 3
  BOTTOM w0.119: UNK2R8.1 418.6,299.42 418.12,298.95 UNK2K1.4
N26486980: length 3
  BOTTOM w0.119: UNK2K1.3 415.92,298.95 415.45,299.42 UNK2R7.2
N26486982: length 3
  BOTTOM w0.119: UNK2K2.3 374.78,250.95 374.3,251.42 UNK2R11.2
N26486983: length 3
  BOTTOM w0.119: UNK2R12.1 377.45,251.42 376.98,250.95 UNK2K2.4
N26486984: length 3
  BOTTOM w0.119: UNK2K4.5 376.98,255.28 377.45,254.8 UNK2R22.1
N26486986: length 3
  BOTTOM w0.119: UNK2K4.3 374.78,266.95 374.3,267.42 UNK2R19.2
N26486987: length 3
  BOTTOM w0.119: UNK2R20.1 377.45,267.42 376.98,266.95 UNK2K4.4
N26486988: length 3
  BOTTOM w0.119: UNK2K4.6 374.78,255.28 374.3,254.8 UNK2R21.2
N26486989: length 3
  BOTTOM w0.119: UNK2K2.5 376.98,239.27 377.45,238.8 UNK2R14.1
N26486990: length 3
  BOTTOM w0.119: UNK2R13.2 374.3,238.8 374.78,239.27 UNK2K2.6
N26487182:
  vias: v1(456.25,233.88)
N26487183:
  vias: v1(451.68,233.88)
N26487190:
  vias: v1(302.38,273.82) v1(302.38,272.66) v1(304.65,271.67)
N26487192:
  vias: v1(302.38,275.98) v1(302.38,274.82) v1(304.65,276.97)
N26487193:
  vias: v1(301.21,276.98) v1(302.38,276.98)
N26487194:
  vias: v1(301.21,271.66) v1(302.38,271.66)
N26487223:
  vias: v1(451.62,232.41)
N26487224:
  vias: v1(451.62,224.79)
N26487285:
  vias: v1(483.1,233.68)
N26487289:
  vias: v1(483.1,241.3)
N26491412:
  vias: v1(491.1,226.67)
N26491416:
  vias: v1(490.86,212.91)
N26491418:
  vias: v1(485.8,212.91)
N26491425:
  vias: v1(477.53,218.59)
N26491459:
  vias: v1(477.43,204.98)
N26491497:
  vias: v1(485.8,226.62)
N26492255:
  vias: v1(462.07,290.83)
N26492261:
  vias: v1(485.35,290.83)
N26492266:
  vias: v1(462.07,274.32)
N26492386:
  vias: v1(478.58,274.32)
N26492392:
  vias: v1(495.09,274.32)
N26492464:
  vias: v1(511.6,290.83)
N26492470:
  vias: v1(478.58,290.83)
N26492603:
  vias: v1(485.35,274.32)
N26492609:
  vias: v1(468.84,274.32)
N26492613:
  vias: v1(468.84,290.83)
N26492615:
  vias: v1(452.33,274.32)
N26492621:
  vias: v1(452.33,290.83)
N26495382: length 3
  BOTTOM w0.119: UNK3K25.3 177.54,149.48 178.01,149.95 UNK3R55.2
N26495383: length 3
  BOTTOM w0.119: UNK3R56.1 178.01,146.81 177.54,147.28 UNK3K25.4
N26495384: length 3
  BOTTOM w0.119: UNK3R57.2 165.4,149.95 165.87,149.48 UNK3K25.6
N26495385: length 3
  BOTTOM w0.119: UNK3K25.5 165.87,147.28 165.4,146.81 UNK3R58.1
N26495387: length 3
  BOTTOM w0.119: UNK3R59.2 194.78,163.67 194.3,163.2 UNK3K26.3
N26495388: length 3
  BOTTOM w0.119: UNK3K26.4 194.3,161 194.78,160.52 UNK3R60.1
N26495389: length 3
  BOTTOM w0.119: UNK3R61.2 182.16,163.67 182.63,163.2 UNK3K26.6
N26495390: length 3
  BOTTOM w0.119: UNK3K26.5 182.63,161 182.16,160.52 UNK3R62.1
N26495392: length 3
  BOTTOM w0.119: UNK3K27.5 199.65,161 199.18,160.52 UNK3R66.1
N26495393: length 3
  BOTTOM w0.119: UNK3R65.2 199.18,163.67 199.65,163.2 UNK3K27.6
N26495400: length 3
  BOTTOM w0.119: UNK3R45.2 165.4,136.74 165.87,136.27 UNK3K22.6
N26495401: length 3
  BOTTOM w0.119: UNK3K22.5 165.87,134.07 165.4,133.6 UNK3R46.1
N26495402: length 3
  BOTTOM w0.119: UNK3K23.3 211.32,149.73 211.79,150.21 UNK3R47.2
N26495403: length 3
  BOTTOM w0.119: UNK3K23.4 211.32,147.53 211.79,147.06 UNK3R48.1
N26495404: length 3
  BOTTOM w0.119: UNK3K23.6 199.65,149.73 199.18,150.21 UNK3R49.2
N26495405: length 3
  BOTTOM w0.119: UNK3R50.1 199.18,147.06 199.65,147.53 UNK3K23.5
N26495407: length 3
  BOTTOM w0.119: UNK3K24.3 194.3,149.48 194.78,149.95 UNK3R51.2
N26495408: length 3
  BOTTOM w0.119: UNK3K24.4 194.3,147.28 194.78,146.81 UNK3R52.1
N26495409: length 3
  BOTTOM w0.119: UNK3R53.2 182.16,149.95 182.63,149.48 UNK3K24.6
N26495410: length 3
  BOTTOM w0.119: UNK3R54.1 182.16,146.81 182.63,147.28 UNK3K24.5
N26495425: length 3
  BOTTOM w0.119: UNK3R102.2 178.01,136.74 177.54,136.27 UNK3K22.3
N26495426: length 3
  BOTTOM w0.119: UNK3R103.1 178.01,133.6 177.54,134.07 UNK3K22.4
N26495427: length 3
  BOTTOM w0.119: UNK3K27.3 211.32,163.2 211.79,163.67 UNK3R104.2
N26495428: length 3
  BOTTOM w0.119: UNK3R105.1 211.79,160.52 211.32,161 UNK3K27.4
N26495543:
  vias: v1(113.55,186.44)
N26495548:
  vias: v1(110.5,186.44)
N26495583: length 3
  BOTTOM w0.119: UNK3K17.3 177.54,190.12 178.01,190.59 UNK3R71.2
N26495584: length 3
  BOTTOM w0.119: UNK3K17.4 177.54,187.92 178.01,187.45 UNK3R72.1
N26495585: length 3
  BOTTOM w0.119: UNK3R74.1 165.4,187.45 165.87,187.92 UNK3K17.5
N26495586: length 3
  BOTTOM w0.119: UNK3R73.2 165.4,190.59 165.87,190.12 UNK3K17.6
N26495587: length 3
  BOTTOM w0.119: UNK3K21.3 211.07,190.12 211.54,190.59 UNK3R75.2
N26495588: length 3
  BOTTOM w0.119: UNK3R76.1 211.54,187.45 211.07,187.92 UNK3K21.4
N26495589: length 3
  BOTTOM w0.119: UNK3K21.5 199.4,187.92 198.92,187.45 UNK3R78.1
N26495590: length 3
  BOTTOM w0.119: UNK3R77.2 198.92,190.59 199.4,190.12 UNK3K21.6
N26495591: length 3
  BOTTOM w0.119: UNK3K29.3 211.32,176.66 211.79,177.13 UNK3R79.2
N26495592: length 3
  BOTTOM w0.119: UNK3K29.4 211.32,174.46 211.79,173.99 UNK3R80.1
N26495593: length 3
  BOTTOM w0.119: UNK3R43.2 199.18,177.13 199.65,176.66 UNK3K29.6
N26495594: length 3
  BOTTOM w0.119: UNK3R44.1 199.18,173.99 199.65,174.46 UNK3K29.5
N26495595: length 3
  BOTTOM w0.119: UNK3R63.2 178.01,163.67 177.54,163.2 UNK3K30.3
N26495596: length 3
  BOTTOM w0.119: UNK3R64.1 178.01,160.52 177.54,161 UNK3K30.4
N26495597: length 3
  BOTTOM w0.119: UNK3R101.1 165.4,160.52 165.87,161 UNK3K30.5
N26495598: length 3
  BOTTOM w0.119: UNK3R100.2 165.4,163.67 165.87,163.2 UNK3K30.6
N26495679: length 3
  BOTTOM w0.119: UNK3K16.3 211.07,204.09 211.54,204.56 UNK3R67.2
N26495680: length 3
  BOTTOM w0.119: UNK3R68.1 211.54,201.42 211.07,201.89 UNK3K16.4
N26495681: length 3
  BOTTOM w0.119: UNK3R70.1 198.92,201.42 199.4,201.89 UNK3K16.5
N26495682: length 3
  BOTTOM w0.119: UNK3R69.2 198.92,204.56 199.4,204.09 UNK3K16.6
N26495704: length 3
  BOTTOM w0.119: UNK3K6.5 182.63,215.35 182.16,214.88 UNK3R30.1
N26495706: length 3
  BOTTOM w0.119: UNK3K6.3 194.3,217.55 194.78,218.02 UNK3R27.2
N26495707: length 3
  BOTTOM w0.119: UNK3K6.4 194.3,215.35 194.78,214.88 UNK3R28.1
N26495708: length 3
  BOTTOM w0.119: UNK3K6.6 182.63,217.55 182.16,218.02 UNK3R29.2
N26495709: length 3
  BOTTOM w0.119: UNK3K7.5 182.63,201.89 182.16,201.42 UNK3R34.1
N26495711: length 3
  BOTTOM w0.119: UNK3K7.3 194.3,204.09 194.78,204.56 UNK3R31.2
N26495712: length 3
  BOTTOM w0.119: UNK3K7.4 194.3,201.89 194.78,201.42 UNK3R32.1
N26495713: length 3
  BOTTOM w0.119: UNK3R33.2 182.16,204.56 182.63,204.09 UNK3K7.6
N26495755: length 3
  BOTTOM w0.119: UNK3K11.3 177.54,204.09 178.01,204.56 UNK3R39.2
N26495756: length 3
  BOTTOM w0.119: UNK3R40.1 178.01,201.42 177.54,201.89 UNK3K11.4
N26495757: length 3
  BOTTOM w0.119: UNK3K8.5 182.63,187.92 182.16,187.45 UNK3R38.1
N26495759: length 3
  BOTTOM w0.119: UNK3K8.6 182.63,190.12 182.16,190.59 UNK3R37.2
N26495760: length 3
  BOTTOM w0.119: UNK3K11.6 165.87,204.09 165.4,204.56 UNK3R41.2
N26495761: length 3
  BOTTOM w0.119: UNK3R42.1 165.4,201.42 165.87,201.89 UNK3K11.5
N26495803: length 3
  BOTTOM w0.119: UNK3R26.1 198.92,214.88 199.4,215.35 UNK3K5.5
N26495805: length 3
  BOTTOM w0.119: UNK3K5.3 211.07,217.55 211.54,218.02 UNK3R23.2
N26495806: length 3
  BOTTOM w0.119: UNK3K5.4 211.07,215.35 211.54,214.88 UNK3R24.1
N26495807: length 3
  BOTTOM w0.119: UNK3K5.6 199.4,217.55 198.92,218.02 UNK3R25.2
N26495828: length 3
  BOTTOM w0.119: UNK3R18.1 261.62,145.5 262.09,145.03 UNK3K3.5
N26495829: length 3
  BOTTOM w0.119: UNK3K3.6 264.29,145.03 264.76,145.5 UNK3R17.2
N26495830: length 3
  BOTTOM w0.119: UNK3R16.1 261.62,132.88 262.09,133.36 UNK3K3.4
N26495831: length 3
  BOTTOM w0.119: UNK3R15.2 264.76,132.88 264.29,133.36 UNK3K3.3
N26495834: length 3
  BOTTOM w0.119: UNK3R10.1 165.4,173.99 165.87,174.46 UNK3K1.5
N26495835: length 3
  BOTTOM w0.119: UNK3K1.6 165.87,176.66 165.4,177.13 UNK3R9.2
N26495836: length 3
  BOTTOM w0.119: UNK3R8.1 178.01,173.99 177.54,174.46 UNK3K1.4
N26495837: length 3
  BOTTOM w0.119: UNK3R7.2 178.01,177.13 177.54,176.66 UNK3K1.3
N26495839: length 3
  BOTTOM w0.119: UNK3K2.3 251.33,130.31 251.81,129.84 UNK3R11.2
N26495840: length 3
  BOTTOM w0.119: UNK3K2.4 249.13,130.31 248.66,129.84 UNK3R12.1
N26495841: length 3
  BOTTOM w0.119: UNK3K4.5 275.3,157.22 274.82,157.69 UNK3R22.1
N26495843: length 3
  BOTTOM w0.119: UNK3K4.3 277.5,145.55 277.97,145.08 UNK3R19.2
N26495844: length 3
  BOTTOM w0.119: UNK3R20.1 274.82,145.08 275.3,145.55 UNK3K4.4
N26495845: length 3
  BOTTOM w0.119: UNK3R21.2 277.97,157.69 277.5,157.22 UNK3K4.6
N26495846: length 3
  BOTTOM w0.119: UNK3K2.5 249.13,141.98 248.66,142.45 UNK3R14.1
N26495847: length 3
  BOTTOM w0.119: UNK3K2.6 251.33,141.98 251.81,142.45 UNK3R13.2
N26496039:
  vias: v1(123.38,197.41)
N26496040:
  vias: v1(127.95,197.41)
N26496047:
  vias: v1(222.38,213.82) v1(222.38,212.66) v1(224.65,211.67)
N26496049:
  vias: v1(222.38,215.98) v1(222.38,214.82) v1(224.65,216.97)
N26496050:
  vias: v1(221.21,216.98) v1(222.38,216.98)
N26496051:
  vias: v1(221.21,211.66) v1(222.38,211.66)
N26496080:
  vias: v1(128.01,182.12)
N26496081:
  vias: v1(128.01,189.74)
N26496142:
  vias: v1(96.53,197.36)
N26496146:
  vias: v1(96.53,189.74)
N26500269:
  vias: v1(88.78,163.72)
N26500273:
  vias: v1(89.02,177.49)
N26500275:
  vias: v1(94.09,177.49)
N26500282:
  vias: v1(102.35,171.81)
N26500316:
  vias: v1(102.45,185.42)
N26500354:
  vias: v1(94.09,163.77)
N26501112:
  vias: v1(111.55,288.29)
N26501118:
  vias: v1(101.81,271.78)
N26501123:
  vias: v1(128.06,271.78)
N26501243:
  vias: v1(75.99,271.78)
N26501249:
  vias: v1(75.99,288.29)
N26501321:
  vias: v1(93.77,271.78)
N26501327:
  vias: v1(93.77,288.29)
N26501460:
  vias: v1(66.25,288.29)
N26501466:
  vias: v1(66.25,271.78)
N26501470:
  vias: v1(84.03,288.29)
N26501472:
  vias: v1(118.32,271.78)
N26501478:
  vias: v1(101.81,288.29)
N26504239: length 3
  BOTTOM w0.119: UNK4R55.2 309.75,156.36 310.22,155.89 UNK4K25.3
N26504240: length 3
  BOTTOM w0.119: UNK4K25.4 312.42,155.89 312.89,156.36 UNK4R56.1
N26504241: length 3
  BOTTOM w0.119: UNK4K25.6 310.22,144.21 309.75,143.74 UNK4R57.2
N26504242: length 3
  BOTTOM w0.119: UNK4K25.5 312.42,144.21 312.89,143.74 UNK4R58.1
N26504244: length 3
  BOTTOM w0.119: UNK4R59.2 356.57,133.44 356.1,132.97 UNK4K26.3
N26504245: length 3
  BOTTOM w0.119: UNK4R60.1 356.57,130.3 356.1,130.77 UNK4K26.4
N26504246: length 3
  BOTTOM w0.119: UNK4K26.6 344.43,132.97 343.96,133.44 UNK4R61.2
N26504247: length 3
  BOTTOM w0.119: UNK4R62.1 343.96,130.3 344.43,130.77 UNK4K26.5
N26504249: length 3
  BOTTOM w0.119: UNK4K27.5 325.92,129.8 326.39,129.33 UNK4R66.1
N26504250: length 3
  BOTTOM w0.119: UNK4R65.2 323.25,129.33 323.72,129.8 UNK4K27.6
N26504257: length 3
  BOTTOM w0.119: UNK4K22.6 389.76,130.05 389.29,129.58 UNK4R45.2
N26504258: length 3
  BOTTOM w0.119: UNK4R46.1 392.43,129.58 391.96,130.05 UNK4K22.5
N26504259: length 3
  BOTTOM w0.119: UNK4R47.2 415.71,142.2 416.18,141.73 UNK4K23.3
N26504260: length 3
  BOTTOM w0.119: UNK4K23.4 418.38,141.73 418.85,142.2 UNK4R48.1
N26504261: length 3
  BOTTOM w0.119: UNK4K23.6 416.18,130.05 415.71,129.58 UNK4R49.2
N26504262: length 3
  BOTTOM w0.119: UNK4K23.5 418.38,130.05 418.85,129.58 UNK4R50.1
N26504264: length 3
  BOTTOM w0.119: UNK4R51.2 402.5,142.2 402.97,141.73 UNK4K24.3
N26504265: length 3
  BOTTOM w0.119: UNK4R52.1 405.64,142.2 405.17,141.73 UNK4K24.4
N26504266: length 3
  BOTTOM w0.119: UNK4R53.2 402.5,129.58 402.97,130.05 UNK4K24.6
N26504267: length 3
  BOTTOM w0.119: UNK4R54.1 405.64,129.58 405.17,130.05 UNK4K24.5
N26504282: length 3
  BOTTOM w0.119: UNK4K22.3 389.76,141.73 389.29,142.2 UNK4R102.2
N26504283: length 3
  BOTTOM w0.119: UNK4K22.4 391.96,141.73 392.43,142.2 UNK4R103.1
N26504284: length 3
  BOTTOM w0.119: UNK4K27.3 323.72,141.47 323.25,141.94 UNK4R104.2
N26504285: length 3
  BOTTOM w0.119: UNK4K27.4 325.92,141.47 326.39,141.94 UNK4R105.1
N26504400:
  vias: v1(465.57,192.28)
N26504405:
  vias: v1(468.62,192.28)
N26504440: length 3
  BOTTOM w0.119: UNK4R71.2 381.16,219.41 381.63,218.94 UNK4K17.3
N26504441: length 3
  BOTTOM w0.119: UNK4K17.4 383.83,218.94 384.31,219.41 UNK4R72.1
N26504442: length 3
  BOTTOM w0.119: UNK4R74.1 384.31,206.8 383.83,207.27 UNK4K17.5
N26504443: length 3
  BOTTOM w0.119: UNK4R73.2 381.16,206.8 381.63,207.27 UNK4K17.6
N26504444: length 3
  BOTTOM w0.119: UNK4R75.2 393.35,157.18 393.83,156.71 UNK4K21.3
N26504445: length 3
  BOTTOM w0.119: UNK4K21.4 396.03,156.71 396.5,157.18 UNK4R76.1
N26504446: length 3
  BOTTOM w0.119: UNK4R78.1 396.5,144.57 396.03,145.04 UNK4K21.5
N26504447: length 3
  BOTTOM w0.119: UNK4K21.6 393.83,145.04 393.35,144.57 UNK4R77.2
N26504448: length 3
  BOTTOM w0.119: UNK4R79.2 407.07,157.18 407.54,156.71 UNK4K29.3
N26504449: length 3
  BOTTOM w0.119: UNK4R80.1 410.21,157.18 409.74,156.71 UNK4K29.4
N26504450: length 3
  BOTTOM w0.119: UNK4R43.2 407.07,144.57 407.54,145.04 UNK4K29.6
N26504451: length 3
  BOTTOM w0.119: UNK4R44.1 410.21,144.57 409.74,145.04 UNK4K29.5
N26504452: length 3
  BOTTOM w0.119: UNK4K30.3 421,156.71 420.53,157.18 UNK4R63.2
N26504453: length 3
  BOTTOM w0.119: UNK4R64.1 423.68,157.18 423.2,156.71 UNK4K30.4
N26504454: length 3
  BOTTOM w0.119: UNK4R101.1 423.68,144.57 423.2,145.04 UNK4K30.5
N26504455: length 3
  BOTTOM w0.119: UNK4K30.6 421,145.04 420.53,144.57 UNK4R100.2
N26504536: length 3
  BOTTOM w0.119: UNK4K16.3 402.08,196.98 402.55,197.45 UNK4R67.2
N26504537: length 3
  BOTTOM w0.119: UNK4K16.4 402.08,194.78 402.55,194.31 UNK4R68.1
N26504538: length 3
  BOTTOM w0.119: UNK4K16.5 390.4,194.78 389.93,194.31 UNK4R70.1
N26504539: length 3
  BOTTOM w0.119: UNK4R69.2 389.93,197.45 390.4,196.98 UNK4K16.6
N26504561: length 3
  BOTTOM w0.119: UNK4R30.1 396.5,177.84 396.03,178.31 UNK4K6.5
N26504563: length 3
  BOTTOM w0.119: UNK4K6.3 393.83,189.99 393.35,190.46 UNK4R27.2
N26504564: length 3
  BOTTOM w0.119: UNK4R28.1 396.5,190.46 396.03,189.99 UNK4K6.4
N26504565: length 3
  BOTTOM w0.119: UNK4R29.2 393.35,177.84 393.83,178.31 UNK4K6.6
N26504566: length 3
  BOTTOM w0.119: UNK4K7.5 413.77,181.32 413.3,180.84 UNK4R34.1
N26504568: length 3
  BOTTOM w0.119: UNK4R31.2 425.92,183.99 425.44,183.52 UNK4K7.3
N26504569: length 3
  BOTTOM w0.119: UNK4K7.4 425.44,181.32 425.92,180.84 UNK4R32.1
N26504570: length 3
  BOTTOM w0.119: UNK4K7.6 413.77,183.52 413.3,183.99 UNK4R33.2
N26504612: length 3
  BOTTOM w0.119: UNK4K11.3 385.57,196.98 386.04,197.45 UNK4R39.2
N26504613: length 3
  BOTTOM w0.119: UNK4K11.4 385.57,194.78 386.04,194.31 UNK4R40.1
N26504614: length 3
  BOTTOM w0.119: UNK4R38.1 409.96,177.84 409.49,178.31 UNK4K8.5
N26504616: length 3
  BOTTOM w0.119: UNK4R37.2 406.82,177.84 407.29,178.31 UNK4K8.6
N26504617: length 3
  BOTTOM w0.119: UNK4K11.6 373.89,196.98 373.42,197.45 UNK4R41.2
N26504618: length 3
  BOTTOM w0.119: UNK4K11.5 373.89,194.78 373.42,194.31 UNK4R42.1
N26504660: length 3
  BOTTOM w0.119: UNK4K5.5 382.82,178.31 383.29,177.84 UNK4R26.1
N26504662: length 3
  BOTTOM w0.119: UNK4R23.2 380.15,190.46 380.62,189.99 UNK4K5.3
N26504663: length 3
  BOTTOM w0.119: UNK4K5.4 382.82,189.99 383.29,190.46 UNK4R24.1
N26504664: length 3
  BOTTOM w0.119: UNK4R25.2 380.15,177.84 380.62,178.31 UNK4K5.6
N26504685: length 3
  BOTTOM w0.119: UNK4K3.5 396.03,161.8 396.5,161.33 UNK4R18.1
N26504686: length 3
  BOTTOM w0.119: UNK4K3.6 393.83,161.8 393.35,161.33 UNK4R17.2
N26504687: length 3
  BOTTOM w0.119: UNK4R16.1 396.5,173.95 396.03,173.48 UNK4K3.4
N26504688: length 3
  BOTTOM w0.119: UNK4K3.3 393.83,173.48 393.35,173.95 UNK4R15.2
N26504691: length 3
  BOTTOM w0.119: UNK4R10.1 423.17,161.33 422.7,161.8 UNK4K1.5
N26504692: length 3
  BOTTOM w0.119: UNK4K1.6 420.5,161.8 420.02,161.33 UNK4R9.2
N26504693: length 3
  BOTTOM w0.119: UNK4K1.4 422.7,173.48 423.17,173.95 UNK4R8.1
N26504694: length 3
  BOTTOM w0.119: UNK4K1.3 420.5,173.48 420.02,173.95 UNK4R7.2
N26504696: length 3
  BOTTOM w0.119: UNK4K2.3 380.62,173.22 380.15,173.69 UNK4R11.2
N26504697: length 3
  BOTTOM w0.119: UNK4K2.4 382.82,173.22 383.29,173.69 UNK4R12.1
N26504698: length 3
  BOTTOM w0.119: UNK4R22.1 409.96,161.33 409.49,161.8 UNK4K4.5
N26504700: length 3
  BOTTOM w0.119: UNK4K4.3 407.29,173.48 406.82,173.95 UNK4R19.2
N26504701: length 3
  BOTTOM w0.119: UNK4R20.1 409.96,173.95 409.49,173.48 UNK4K4.4
N26504702: length 3
  BOTTOM w0.119: UNK4K4.6 407.29,161.8 406.82,161.33 UNK4R21.2
N26504703: length 3
  BOTTOM w0.119: UNK4K2.5 382.82,161.55 383.29,161.08 UNK4R14.1
N26504704: length 3
  BOTTOM w0.119: UNK4R13.2 380.15,161.08 380.62,161.55 UNK4K2.6
N26504896:
  vias: v1(456.25,190.45)
N26504897:
  vias: v1(451.68,190.45)
N26504904:
  vias: v1(302.38,213.82) v1(302.38,212.66) v1(304.65,211.67)
N26504906:
  vias: v1(302.38,215.98) v1(302.38,214.82) v1(304.65,216.97)
N26504907:
  vias: v1(301.21,216.98) v1(302.38,216.98)
N26504908:
  vias: v1(301.21,211.66) v1(302.38,211.66)
N26504937:
  vias: v1(451.62,188.98)
N26505003:
  vias: v1(483.1,197.87)
N26509126:
  vias: v1(491.1,183.24)
N26509130:
  vias: v1(490.86,169.47)
N26509132:
  vias: v1(485.8,169.47)
N26509139:
  vias: v1(477.53,175.15)
N26509173:
  vias: v1(477.43,161.55)
N26509211:
  vias: v1(485.8,183.19)
N26509969:
  vias: v1(511.6,274.32)
N26509975:
  vias: v1(518.37,290.83)
N26509980:
  vias: v1(528.11,274.32)
N26510100:
  vias: v1(478.58,257.81)
N26510106:
  vias: v1(528.11,257.81)
N26510178:
  vias: v1(511.6,257.81)
N26510184:
  vias: v1(495.09,257.81)
N26510317:
  vias: v1(518.37,257.81)
N26510323:
  vias: v1(468.84,257.81)
N26510327:
  vias: v1(485.35,257.81)
N26510329:
  vias: v1(518.37,274.32)
N26510335:
  vias: v1(501.86,274.32)

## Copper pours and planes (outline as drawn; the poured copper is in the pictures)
GND on L02_DGND, L03_SIGNAL, L04_DGND, L05_SIGNAL, L06_DGND, L07_SIGNAL, L08_DGND, L10_DGND, L12_DGND, L14_DGND, L16_DGND, L19_DGND, L21_DGND, L23_DGND, L25_DGND, L27_DGND, L28_SIGNAL, L29_DGND, L30_SIGNAL, L31_DGND: 1.02,1.27 1.02,427.99 205.54,427.99 216.92,422.32 228.3,427.99 352.84,427.99 364.23,422.27 375.62,427.99 580.13,427.99 580.13,1.27 301.95,1.27 290.57,6.93 279.19,1.27
(no net) on L32_SIGNAL, L33_DGND: 1.02,1.27 1.02,427.99 205.54,427.99 216.92,422.32 228.3,427.99 352.84,427.99 364.23,422.27 375.62,427.99 580.13,427.99 580.13,1.27 301.95,1.27 290.57,6.93 279.19,1.27

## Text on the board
User.Comments: CR_SS_6 | CR_2_2 | CR_RELAY_19 | CR_4_2 | CR_3_1 | CR_2_3 | CR_UNNAMED_2 | CR_UNNAMED_3 | CR_QQ_28 | CR_A_23 | CR_5_1 | CR_5_2 | CR_QQ_12 | CR_QQ_11 | CR_A_28 | CR_A_21 | CR_A_25 | CR_A_26 | CR_A_30 | CR_A_32 | CR_A_22 | CR_A_24 | CR_A_27 | CR_A_29 | CR_A_31 | CR_A_20
